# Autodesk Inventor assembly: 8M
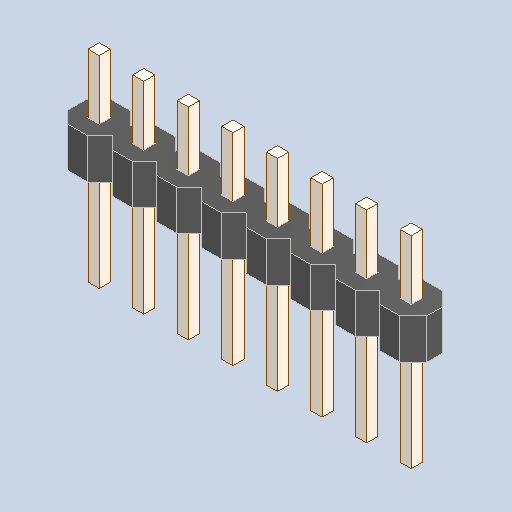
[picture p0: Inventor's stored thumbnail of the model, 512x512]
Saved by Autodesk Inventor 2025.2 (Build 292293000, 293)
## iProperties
Created: 2025-04
Part Number: 8M
Description: PART--DESC
Document SubType Name: Assembly
Designer: BennF
Author: BennF
Revision Number: NONE
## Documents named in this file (3)
- C:\Users\BennF\Nextcloud\Benutzer\CNC JarBeRi\existing parts\Electronics\RepRap A4988 Shied (USE WITHOUT ARDUINO)\reprap-a4988-1.snapshot.1\RepRap\RepRap\8M_1.iam
- C:\Users\BennF\Nextcloud\Benutzer\CNC JarBeRi\existing parts\Electronics\RepRap A4988 Shied (USE WITHOUT ARDUINO)\reprap-a4988-1.snapshot.1\RepRap\RepRap\8M Geometry.ipt
- C:\Users\BennF\Nextcloud\Benutzer\CNC JarBeRi\existing parts\Electronics\RepRap A4988 Shied (USE WITHOUT ARDUINO)\reprap-a4988-1.snapshot.1\RepRap\RepRap\pin4.ipt
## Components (2 placed, 2 different names)
1. 8M Geometry
2. pin4
